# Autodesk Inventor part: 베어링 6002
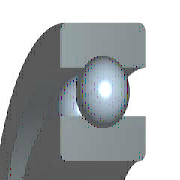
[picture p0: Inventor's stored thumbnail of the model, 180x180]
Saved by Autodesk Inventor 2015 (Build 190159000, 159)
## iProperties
IsCustomPart: 0
Created: 2015-10
Part Number: 베어링 6002
Material: 강, 연강
Description: 깊은 그루브 볼 베어링
Document SubType Name: Modeling
Standard: KS B 2023
Designer: mdu
Standards Organization: KS
Language: ko-KR
Size Designation: 6002 - 15 x 32 x 9
Categories: <MemberInstance><Categories><Category DisplayName="샤프트 부품" InternalName="7f7aeb1f-a693-4053-b835-cee3144e0d98" Mnemonic="SHFT"><Category DisplayName="베어링" Inter
Density: 1 g/cm^3
Appearance: 강철
Author: mdu
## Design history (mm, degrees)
sketch "스케치" dims "d0" = 4.42 (= -0.26 x WD + 0.26 x BD)
  geometry: L1 (2.29, 11.75)-(6.71, 11.75); L2 (4.5, 11.75)-(4.5, 9.54); L3 (4.5, 11.75)-(4.5, 13.96); L4 (2.858, 10.271)-(0, 10.271); L5 (0, 7.5)-(9, 7.5); L6 (2.858, 13.229)-(0, 13.229); L7 (0, 16)-(9, 16); L8 (9, 7.5)-(9, 10.271); L9 (6.142, 10.271)-(9, 10.271); L10 (6.142, 13.229)-(9, 13.229); L11 (9, 16)-(9, 13.229); L12 (-1.4, 0)-(8.4, 0) reference; L13 (0, -0.3)-(0, 5.3) reference
  constraints: 22 end point, 4 point on line, 2 collinear, 2 perpendicular, 2 symmetric about line, 1 midpoint, 1 parallel, 14 other
  dimensions: "d9" = 15 diameter of L5 L12 (= WD); "d11" = 32 diameter of L7 L12 (= BD); "d12" = 9 distance between parallel lines of L8 L13 (= KB); "d13" = 20.542 diameter of L9 L12 (= 0.326 x BD + 0.674 x WD)
revolve "본체" stored, may be unused: angle "d6" = 90 deg
revolve "볼" stored, may be unused: angle "d7" = 90 deg
pattern_circular "IDS_ARRAYBALL[SIMPL:T]" dims angle "d3" = 360 deg
body "Solid1"
fillet "모깎기1" dims "d1" = 0.3 (= KRS)
other parameters: "WD" = 15 [user parameter; used in 5 equation terms], "BD" = 32 [user parameter; used in 5 equation terms], "KB" = 9 [user parameter; used in 1 equation term], "KRS" = 0.3 [user parameter; used in 1 equation term], "d4" = 0, "d5" = 0, "d8" = 0, "d14" = 0, "d15" = 0, "BBA" = 0 [user parameter], "BC0" = 2850000 [user parameter], "BC" = 5590000 [user parameter], "BR" = 16 (= 0.5 x BD) [user parameter], "WR" = 7.5 (= 0.5 x WD) [user parameter]
